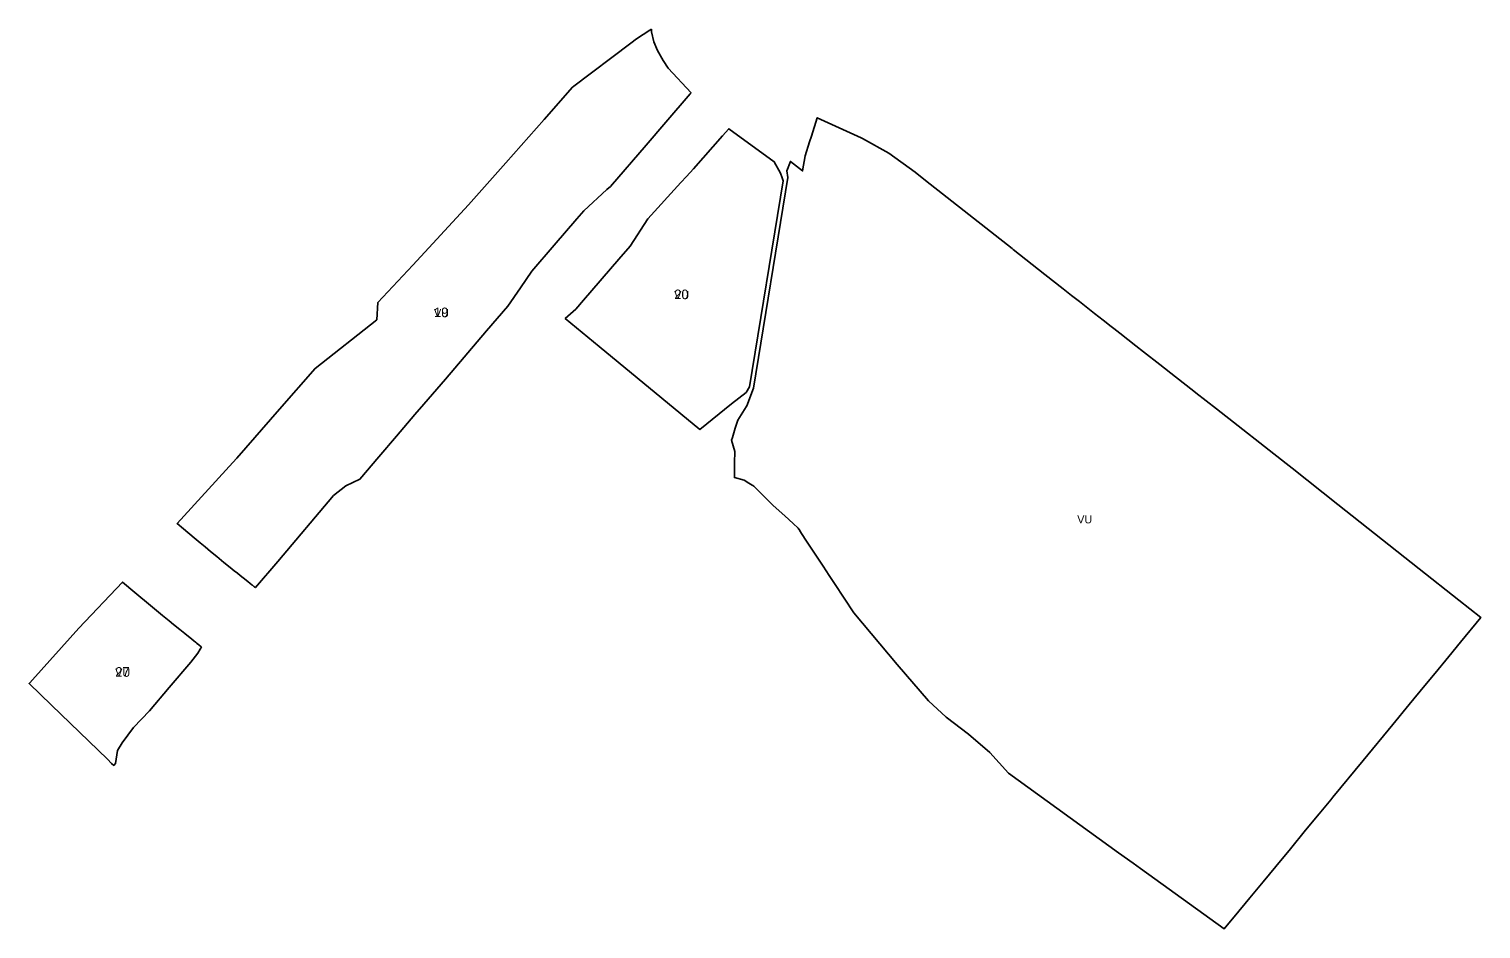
# Model space of a CAD drawing. Extents: x -537011 to -534997, y -1176103 to -1174159.
# Drawn here: x -535923 to -535016, y -1175070 to -1174508 of the extents above; entities that cross this region are included whole.
import ezdxf

# ---------------------------------------------------------------- set-up
doc = ezdxf.new("R2010")
doc.units = 0
for name, color, linetype in [('90570013', 7, 'Continuous'), ('90570023', 7, 'Continuous'), ('ID_navrh', 7, 'Continuous')]:
    doc.layers.add(name, color=color, linetype=linetype)

msp = doc.modelspace()

# ---------------------------------------------------------------- linework, layer by layer
at = {"layer": '90570013'}
msp.add_lwpolyline([(-535028.38, -1174891.27), (-535035.75, -1174900.21), (-535044.3, -1174910.58), (-535050.64, -1174918.28), (-535060.48, -1174930.22), (-535070.78, -1174942.72), (-535089.3, -1174965.19), (-535108.22, -1174988.14), (-535109.44, -1174989.63), (-535116.71, -1174998.43), (-535125.23, -1175008.74), (-535134.77, -1175020.29), (-535143.93, -1175031.38), (-535151.84, -1175040.95), (-535160.18, -1175051.04), (-535169.92, -1175062.83), (-535175.34, -1175069.39), (-535176.19, -1175070.42), (-535219.53, -1175039.08), (-535228.44, -1175032.64), (-535233.05, -1175029.31), (-535242.13, -1175022.75), (-535310.83, -1174973.08), (-535322.59, -1174960.24), (-535335.96, -1174948.68), (-535349.99, -1174938.08), (-535360.99, -1174927.82), (-535380.6, -1174905.1), (-535407.58, -1174872.88), (-535419.7, -1174854.51), (-535422.98, -1174849.53), (-535426.85, -1174843.66), (-535430.46, -1174838.18), (-535433.77, -1174833.16), (-535437.91, -1174826.88), (-535441.42, -1174821.56), (-535441.32, -1174821.49), (-535442.45, -1174820), (-535445.58, -1174817.12), (-535450.76, -1174812.35), (-535457.94, -1174805.74), (-535460.66, -1174803.04), (-535463.55, -1174800.18), (-535470.08, -1174793.7), (-535470.76, -1174793.28), (-535471.13, -1174793.04), (-535473.12, -1174791.77), (-535476.14, -1174789.91), (-535482.28, -1174788.36), (-535482.11, -1174779.15), (-535481.97, -1174771.97), (-535484.03, -1174765.07), (-535483.52, -1174763.4), (-535481.66, -1174757.38), (-535480.16, -1174752.5), (-535474.91, -1174744.23), (-535474.51, -1174743.6), (-535470.32, -1174732.58), (-535448.76, -1174600.74), (-535449.55, -1174596.67), (-535447.21, -1174590.8), (-535439.6, -1174596.68), (-535438.02, -1174587.22), (-535435.27, -1174578.62), (-535434.12, -1174575.02), (-535430.46, -1174563.51), (-535403.06, -1174576.02), (-535402.21, -1174576.49), (-535385.62, -1174585.63), (-535369.33, -1174597.57), (-535362.87, -1174602.65), (-535308.72, -1174645.31), (-535307.95, -1174645.91), (-535288.12, -1174661.46), (-535276.83, -1174670.32), (-535271.47, -1174674.53), (-535266.49, -1174678.43), (-535257.11, -1174685.79), (-535251.68, -1174690.05), (-535246.75, -1174693.92), (-535245.09, -1174695.22), (-535241.43, -1174698.08), (-535236.44, -1174701.98), (-535231.33, -1174705.98), (-535226.54, -1174709.73), (-535216.41, -1174717.66), (-535206.62, -1174725.33), (-535195.16, -1174734.3), (-535193.83, -1174735.34), (-535180.95, -1174745.42), (-535137.34, -1174779.47), (-535133.64, -1174782.42), (-535105.18, -1174805.1), (-535054.2, -1174845.36), (-535029.37, -1174864.97), (-535015.64, -1174875.82)], close=True, dxfattribs=at)
at = {"layer": '90570023'}
for points in [[(-535534.06, -1174508.07), (-535534.01, -1174508.81), (-535533.96, -1174509.74), (-535532.6, -1174516.01), (-535530.21, -1174521.58), (-535526.78, -1174527.73), (-535523.54, -1174532.47), (-535509.32, -1174547.89), (-535509.96, -1174548.62), (-535525.17, -1174566.32), (-535537.48, -1174580.61), (-535559.75, -1174606.46), (-535561.88, -1174608.41), (-535576.31, -1174621.58), (-535580.76, -1174626.75), (-535594.83, -1174643.09), (-535608.9, -1174659.44), (-535615.96, -1174669.8), (-535623.74, -1174681.22), (-535637.08, -1174696.76), (-535662.9, -1174726.86), (-535668.24, -1174733.08), (-535670.89, -1174736.17), (-535676.25, -1174742.42), (-535681.87, -1174749), (-535693.46, -1174762.57), (-535704.49, -1174775.48), (-535716.26, -1174789.26), (-535725.13, -1174793.48), (-535732.8, -1174799.58), (-535767.59, -1174840.78), (-535781.63, -1174857.08), (-535781.92, -1174856.85), (-535782.05, -1174856.75), (-535782.12, -1174856.69), (-535782.17, -1174856.65), (-535782.24, -1174856.6), (-535782.28, -1174856.57), (-535782.32, -1174856.54), (-535782.32, -1174856.53), (-535782.33, -1174856.53), (-535782.34, -1174856.52), (-535782.35, -1174856.52), (-535782.35, -1174856.51), (-535782.36, -1174856.5), (-535782.38, -1174856.49), (-535782.39, -1174856.48), (-535782.4, -1174856.47), (-535782.41, -1174856.46), (-535782.42, -1174856.46), (-535782.43, -1174856.45), (-535782.46, -1174856.43), (-535782.48, -1174856.41), (-535782.58, -1174856.33), (-535782.73, -1174856.21), (-535782.97, -1174856.02), (-535783.42, -1174855.66), (-535783.63, -1174855.5), (-535783.87, -1174855.31), (-535784.8, -1174854.56), (-535786.38, -1174853.31), (-535789.25, -1174851.01), (-535791.04, -1174849.58), (-535792.87, -1174848.11), (-535794.79, -1174846.56), (-535797.31, -1174844.54), (-535801.28, -1174841.34), (-535805.65, -1174837.7), (-535809.67, -1174834.47), (-535812.95, -1174831.73), (-535816.15, -1174829.08), (-535819.89, -1174825.91), (-535826.64, -1174820.33), (-535830.57, -1174816.98), (-535795.7, -1174778.85), (-535793.3, -1174776.23), (-535766.49, -1174745.54), (-535744.28, -1174720.12), (-535705.75, -1174689.68), (-535704.99, -1174678.9), (-535683.3, -1174655.54), (-535648.45, -1174618), (-535625.08, -1174591.58), (-535601.2, -1174564.58), (-535583.39, -1174544.45), (-535547.02, -1174516.87), (-535543.45, -1174514.17), (-535535.15, -1174508.78)], [(-535474.82, -1174735.18), (-535484.01, -1174742.28), (-535503.82, -1174758.26), (-535566.78, -1174706.43), (-535587.98, -1174688.98), (-535581.4, -1174683.2), (-535576.48, -1174677.51), (-535554.37, -1174651.88), (-535547.33, -1174643.72), (-535536.25, -1174626.67), (-535515.65, -1174604.06), (-535512.09, -1174600.14), (-535507.87, -1174595.51), (-535489.61, -1174574.77), (-535485.78, -1174570.42), (-535457.32, -1174590.95), (-535453.38, -1174598.07), (-535452.36, -1174600.98), (-535451.68, -1174602.89), (-535472.77, -1174731.72)], [(-535869.09, -1174967.04), (-535870.12, -1174968.27), (-535871.51, -1174966.94), (-535874.11, -1174964.42), (-535909.05, -1174930.65), (-535923.09, -1174917.08), (-535922.59, -1174916.55), (-535920.96, -1174914.72), (-535892.04, -1174882.37), (-535864.6, -1174853.66), (-535856.91, -1174860.12), (-535847.18, -1174868.32), (-535839.59, -1174874.57), (-535835.45, -1174877.94), (-535832.7, -1174880.19), (-535828.91, -1174883.28), (-535825.72, -1174885.85), (-535823.53, -1174887.61), (-535822.62, -1174888.35), (-535820.1, -1174890.37), (-535819.13, -1174891.14), (-535818.47, -1174891.67), (-535818.12, -1174891.95), (-535817.85, -1174892.16), (-535816.96, -1174892.85), (-535815.51, -1174894.03), (-535815.31, -1174894.19), (-535815.76, -1174895.01), (-535816.08, -1174895.56), (-535817.52, -1174898.06), (-535821.9, -1174903.73), (-535835.42, -1174919.52), (-535847.89, -1174934.15), (-535857.7, -1174944.51), (-535864.89, -1174954.2), (-535867.71, -1174958.89)]]:
    msp.add_lwpolyline(points, close=True, dxfattribs=at)

# ---------------------------------------------------------------- texts
at = {"layer": '90570013'}
msp.add_text('VU', height=5, rotation=0, dxfattribs=at).set_placement((-535267.952, -1174816.965))
at = {"layer": '90570023'}
for rotation, p in [(0, (-535519.83, -1174676.864)), (360, (-535669.945, -1174688.111)), (360, (-535869.2, -1174912.822))]:
    msp.add_text('VU', height=5, rotation=rotation, dxfattribs=at).set_placement(p)
at = {"layer": 'ID_navrh'}
for s, p in [('20', (-535519.83, -1174676.864)), ('19', (-535669.945, -1174688.111)), ('27', (-535869.2, -1174912.822))]:
    msp.add_text(s, height=6, rotation=360, dxfattribs=at).set_placement(p)

doc.saveas('drawing.dxf')
